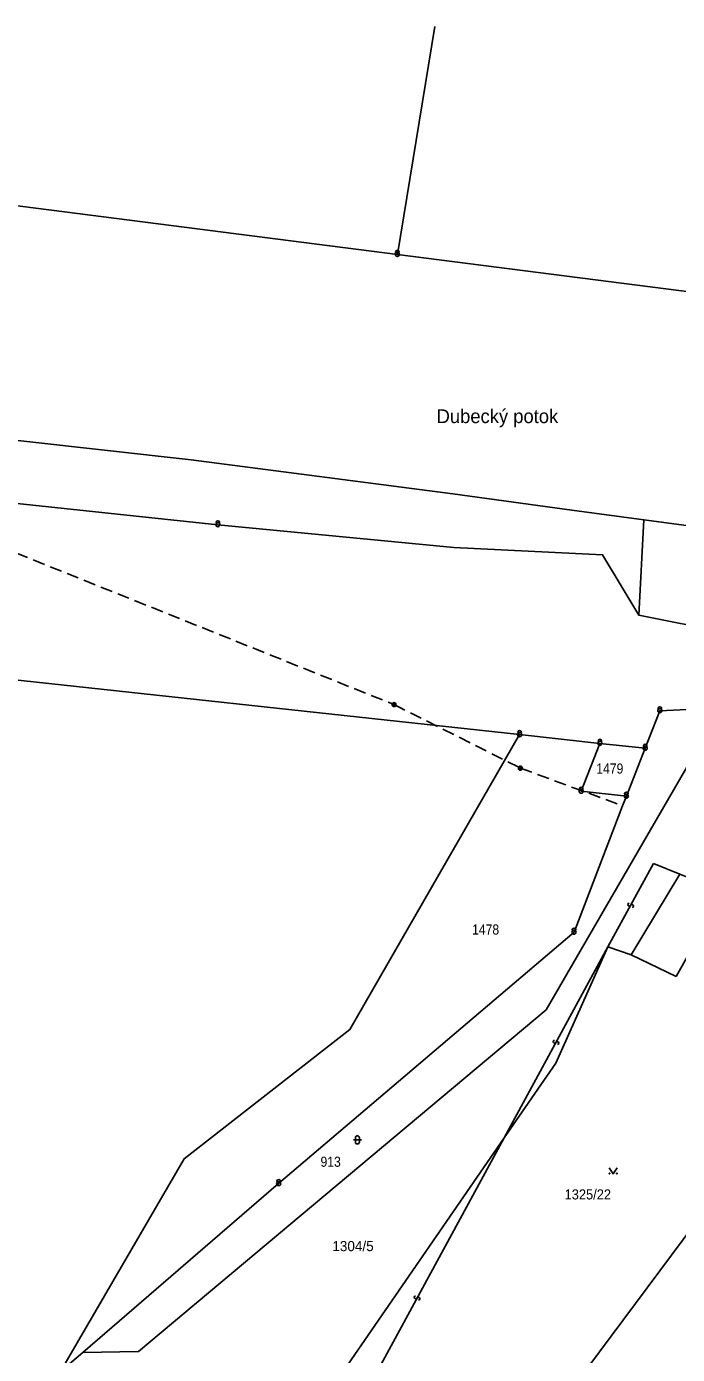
# Model space of a CAD drawing. Extents: x -871901 to -870967, y -1075952 to -1074892.
# Drawn here: x -871201.3 to -871136.9, y -1075290 to -1075158.8 of the extents above; entities that cross this region are included whole.
import ezdxf

# ---------------------------------------------------------------- set-up
doc = ezdxf.new("R2010")
doc.units = 0
doc.header["$LTSCALE"] = 0.4
doc.linetypes.add('MEDIUM_DASHED', pattern=[4.5, 3, -1.5])
for name, color, linetype, lineweight in [('1', 7, 'Continuous', 25), ('12', 7, 'MEDIUM_DASHED', 25), ('24', 7, 'Continuous', 25), ('25', 7, 'Continuous', 25), ('26', 7, 'Continuous', 25), ('4', 7, 'Continuous', 25)]:
    doc.layers.add(name, color=color, linetype=linetype, lineweight=lineweight)
doc.layers.add('15', color=7, linetype='Continuous')
doc.layers.add('18', color=7, linetype='Continuous')

msp = doc.modelspace()

# ---------------------------------------------------------------- linework, layer by layer
at = {"layer": '1'}
for p, q in [((-871164.62, -1075181.27), (-871160.9, -1075158.75)), ((-871265.65, -1075168.37), (-871164.62, -1075181.27)), ((-871164.62, -1075181.27), (-871127.17, -1075186.06)), ((-871149.91, -1075255.96), (-871132.62, -1075226.11)), ((-871152.53, -1075228.75), (-871144.59, -1075229.61)), ((-871147.15, -1075248.28), (-871142.34, -1075235.78)), ((-871141.5, -1075250.52), (-871136.68, -1075242.53)), ((-871176.36, -1075273.13), (-871147.15, -1075248.28)), ((-871156.43, -1075305.59), (-871115.7, -1075250.9)), ((-871141.5, -1075250.52), (-871137.04, -1075252.66)), ((-871137.04, -1075252.66), (-871135.52, -1075249.95)), ((-871154.05, -1075268.6), (-871148.96, -1075261.22)), ((-871174.28, -1075297.93), (-871154.05, -1075268.6)), ((-871195.74, -1075289.82), (-871176.36, -1075273.13))]:
    msp.add_line(p, q, dxfattribs=at)
for points in [[(-871590.36, -1075167.06), (-871564.6, -1075180.17), (-871498.95, -1075191.88), (-871324.15, -1075210.15), (-871152.53, -1075228.75), (-871169.32, -1075257.9), (-871185.72, -1075270.67), (-871197.94, -1075291.72)], [(-871140.23, -1075207.5), (-871147.35, -1075206.55), (-871159.14, -1075204.95), (-871185.02, -1075201.57), (-871218.75, -1075197.81), (-871245.79, -1075194.55), (-871331.72, -1075185.46), (-871410.01, -1075176.94)], [(-871300.12, -1075195.6), (-871219.01, -1075204.11), (-871182.37, -1075208)], [(-871132.14, -1075218.66), (-871140.73, -1075216.95), (-871140.23, -1075207.5)], [(-871140.23, -1075207.5), (-871135.53, -1075208.13), (-871130.44, -1075213.21), (-871123.91, -1075214.69)], [(-871182.37, -1075208), (-871159.03, -1075210.24), (-871144.33, -1075210.97), (-871140.73, -1075216.95)], [(-871142.34, -1075235.78), (-871141.97, -1075234.83), (-871140.11, -1075230.1), (-871138.66, -1075226.39), (-871132.62, -1075226.11)], [(-871140.11, -1075230.1), (-871144.59, -1075229.61), (-871146.44, -1075234.35), (-871141.97, -1075234.83)], [(-871148.96, -1075261.22), (-871143.79, -1075249.74), (-871141.5, -1075250.52)], [(-871195.74, -1075289.82), (-871190.23, -1075289.74), (-871149.91, -1075255.96)], [(-871198.89, -1075304.69), (-871198.62, -1075300.91), (-871198.28, -1075296.29), (-871197.94, -1075291.72), (-871195.74, -1075289.82)]]:
    msp.add_lwpolyline(points, dxfattribs=at)
at = {"layer": '12'}
for p, q in [((-871219.01, -1075204.11), (-871164.94, -1075225.78)), ((-871164.94, -1075225.78), (-871152.45, -1075232.06)), ((-871152.45, -1075232.06), (-871142.34, -1075235.78))]:
    msp.add_line(p, q, dxfattribs=at)
at = {"layer": '24'}
for centre, radius in [((-871164.6195, -1075181.2695), 0.2005), ((-871164.6195, -1075181.2695), 0.00851), ((-871182.3695, -1075207.9995), 0.2005), ((-871182.3695, -1075207.9995), 0.00851), ((-871138.6595, -1075226.3895), 0.2005), ((-871138.6595, -1075226.3895), 0.00851), ((-871152.5295, -1075228.7495), 0.2005), ((-871152.5295, -1075228.7495), 0.00851), ((-871144.5895, -1075229.6095), 0.2005), ((-871144.5895, -1075229.6095), 0.00851), ((-871140.1095, -1075230.0995), 0.2005), ((-871140.1095, -1075230.0995), 0.00851), ((-871146.4395, -1075234.3495), 0.2005), ((-871146.4395, -1075234.3495), 0.00851), ((-871141.9695, -1075234.8295), 0.2005), ((-871141.9695, -1075234.8295), 0.00851), ((-871147.1495, -1075248.2795), 0.2005), ((-871147.1495, -1075248.2795), 0.00851), ((-871176.3595, -1075273.1295), 0.2005), ((-871176.3595, -1075273.1295), 0.00851)]:
    msp.add_circle(centre, radius, dxfattribs=at)
for centre in [(-871164.6198, -1075181.0436), (-871182.3698, -1075207.7736), (-871138.6598, -1075226.1636), (-871152.5298, -1075228.5236), (-871144.5898, -1075229.3836), (-871140.1098, -1075229.8736), (-871146.4398, -1075234.1236), (-871141.9698, -1075234.6036), (-871147.1498, -1075248.0536), (-871176.3598, -1075272.9036)]:
    msp.add_arc(centre, 0.1746, 328.19485, 209.95045, dxfattribs=at)
at = {"layer": '25'}
for p, q in [((-871168.97, -1075268.809), (-871168.169, -1075268.809)), ((-871168.77, -1075269.009), (-871168.77, -1075268.609)), ((-871168.369, -1075268.609), (-871168.369, -1075269.009))]:
    msp.add_line(p, q, dxfattribs=at)
msp.add_lwpolyline([(-871143.68, -1075271.569), (-871143.28, -1075272.17), (-871142.879, -1075271.569)], dxfattribs=at)
for centre in [(-871143.64, -1075272.13), (-871142.919, -1075272.13)]:
    msp.add_circle(centre, 0.04, dxfattribs=at)
for centre, radius, start, end in [((-871141.6782, -1075245.5483), 0.1469, 98.63032, 330.64487), ((-871141.4213, -1075245.6921), 0.1476, 278.57136, 150.83644), ((-871149.0482, -1075259.0983), 0.1469, 98.63032, 330.64487), ((-871148.7913, -1075259.2421), 0.1476, 278.57136, 150.83644), ((-871168.5695, -1075268.6095), 0.2005, 0.101, 180.00143), ((-871168.5695, -1075269.0095), 0.2005, 180.10243, 0.00286), ((-871162.7982, -1075284.3683), 0.1469, 98.63032, 330.64487), ((-871162.5413, -1075284.5121), 0.1476, 278.57136, 150.83644)]:
    msp.add_arc(centre, radius, start, end, dxfattribs=at)
at = {"layer": '26'}
for centre, radius in [((-871164.9395, -1075225.7795), 0.2005), ((-871164.9395, -1075225.7795), 0.1205), ((-871164.9395, -1075225.7795), 0.0605), ((-871152.4495, -1075232.0595), 0.2005), ((-871152.4495, -1075232.0595), 0.1205), ((-871152.4495, -1075232.0595), 0.0605)]:
    msp.add_circle(centre, radius, dxfattribs=at)
at = {"layer": '4'}
for p, q in [((-871143.79, -1075249.74), (-871139.3, -1075241.49)), ((-871154.05, -1075268.6), (-871143.79, -1075249.74)), ((-871171.28, -1075300.27), (-871154.05, -1075268.6))]:
    msp.add_line(p, q, dxfattribs=at)
msp.add_lwpolyline([(-871139.3, -1075241.49), (-871136.68, -1075242.53), (-871130.08, -1075245.17)], dxfattribs=at)

# ---------------------------------------------------------------- texts
at = {"layer": '15'}
msp.add_text('Dubecký potok', height=1.36, dxfattribs=at).set_placement((-871160.74, -1075197.95))
at = {"layer": '18'}
for s, width, p in [('1479', 0.9, (-871144.95, -1075232.6)), ('1478', 0.9, (-871157.23, -1075248.51)), ('913', 0.9, (-871172.22, -1075271.47)), ('1325/22', 0.95, (-871148.08, -1075274.7))]:
    msp.add_text(s, height=1, dxfattribs=dict(at, width=width)).set_placement(p)
msp.add_text('1304/5', height=1, dxfattribs=at).set_placement((-871171.05, -1075279.81))

doc.saveas('drawing.dxf')
